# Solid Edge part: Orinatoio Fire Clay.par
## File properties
Title: Orinatoio
Author: DESYS
Template: iso part.par
Last saved by: s.pallini
Revision: 16
Application: Solid Edge
Tipo di contenuto documento: 0
Accuracy: 0,990
Document Number: 2014
Revision: 0
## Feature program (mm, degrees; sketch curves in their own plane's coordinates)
lofted protrusion "unnamed LoftedProtrusion 1"
sketch for "unnamed Protrusion 1" plane through (0, 0, 0) normal (0, -1, 0) x-axis (1, 0, 0)
  line (-19.3163, -75) -> (-440, -75)
  line (-440, -75) -> (-440, 75)
  line (-440, 75) -> (-19.3163, 75)
  line (-19.3163, 75) -> (-19.3163, -75)
  dimension (linear) = 440
extrude "unnamed Protrusion 1" add finite 155 along -normal
lofted cutout "unnamed LoftedCutout 1"
sketch for "ScavoEstrusione_1" plane through (43.6224, 155.3688, -0.1014) normal (0.615661, 0.788011, 0) x-axis (0, 0, -1)
  bspline degree 3 poles (0.466, 143.238) (-31.5699, 143.3592) (-62.3959, 125.2931) (-103.6679, 69.2618) (-114.958, 31.5333) (-115.2445, -44.1871) (-104.2401, -81.9998) (-63.3932, -138.3418) (-32.7047, -156.6406) (31.3671, -156.8829) (62.1931, -138.8169) (103.4651, -82.7856) (114.7552, -45.0571) (115.0417, 30.6633) (104.0373, 68.4761) (63.1903, 124.818) (32.5019, 143.1168) (0.466, 143.238) knots 0 0.125 0.25 0.375 0.5 0.625 0.75 0.875 1 multiplicities 4 2 2 2 2 2 2 2 4
extrude "ScavoEstrusione_1" cut finite 55 along -normal
fillet "Rotondo_2" radius 25
thinwall "Spessoramento_7"  Thickness = 10 mm
sketch for "unnamed Protrusion 2" plane through (-104.9962, 0, 0) normal (0, -1, 0) x-axis (0, 0, 1)
  line (-96.4961, -226.0512) -> (96.4961, -226.0512)
extrude "unnamed Protrusion 2" add through along -normal
fillet "Rotondo_3" radius 25
sketch for "Foro_1" plane through (-104.9962, 0, 0.101) normal (0, -1, 0) x-axis (0, 0, 1)
  hole centre (-0.101, -269.9962) bore radius 15
hole "Foro_1" diameter 30 finite  CounterBoreDepth = 12 mm
sketch for "ProtrusioneEstrusa_4" plane through (-104.9962, 50, 0.101) normal (0, -1, 0) x-axis (-1, 0, 0)
  circle centre (40.0038, 0.101) radius 22.5
extrude "ProtrusioneEstrusa_4" add finite 90 along -normal  Profile_Plane1_Distance = 50 mm
sketch for "Foro_2" plane through (-125, 50, 0) normal (0, -1, 0) x-axis (-1, 0, 0)
  hole centre (20, 0) bore radius 17.5
hole "Foro_2" diameter 35 finite
sketch for "unnamed Protrusion 3" #1 plane through (-104.9962, 0, 0.101) normal (0, -1, 0) x-axis (-1, 0, 0)
  line (302.5038, 65.101) -> (325.0038, 65.101)
  line (325.0038, 65.101) -> (325.0038, 42.601)
sketch for "unnamed Protrusion 3" #2 plane through (-104.9962, 0, 0.101) normal (0, -1, 0) x-axis (-1, 0, 0)
  line (325.0038, -64.899) -> (302.5038, -64.899)
  line (325.0038, -42.399) -> (325.0038, -64.899)
extrude "unnamed Protrusion 3" add through along -normal
sketch for "Foro_3" plane through (-104.9962, 0, 0.101) normal (0, -1, 0) x-axis (-1, 0, 0)
  hole centre (320.0038, 60.101) bore radius 5
hole "Foro_3" diameter 10 finite
sketch for "unnamed Hole 1" plane through (-104.9962, 0, 0.101) normal (0, -1, 0) x-axis (-1, 0, 0)
  hole centre (320.0038, -59.899) bore radius 5
hole "unnamed Hole 1" finite
pattern "unnamed Pattern 1" of "Foro_3", "unnamed Hole 1"
fillet "Rotondo_6" radius 10
fillet "Rotondo_7" radius 10
fillet "Rotondo_8" radius 3
fillet "Rotondo_9" radius 10
fillet "Rotondo_10" radius 5
fillet "Rotondo_11" radius 10
sketch for "unnamed Protrusion 4" plane through (-132.686, 140, 0.1259) normal (0, 1, 0) x-axis (-1, 0, 0)
  line (-2.473, 16.8328) -> (-2.473, 9.2334)
  line (-2.473, -9.4852) -> (-2.473, -17.0846)
extrude "unnamed Protrusion 4" add to key point along +normal
fillet "Rotondo_12" radius 5
fillet "Rotondo_13" radius 3
fillet "Rotondo_14" radius 3
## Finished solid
Body 1: solid body, 89 faces, 181 edges, 94 vertices.
  Faces by surface: plane 26, blend 24, cylinder 24, torus 7, offset 3, sphere 2, spline 2, swept 1
  Edges by curve: intersection 71, circle 60, line 48, ellipse 1, spline 1
Bounding box of the edges (mm; curved faces can reach further): 693.085 x 301.754 x 298.185, from (-440, 0, -149.094) to (253.0847, 301.754, 149.0913).
Cylindrical faces by radius (mm): R3 x6, R5 x2, R10 x8, R15 x1, R17.5 x2, R22.5 x3, R25 x2
Toroidal faces (ring radius, tube radius in mm): R7 r3 x2, R19.5 r3 x3, R32.5 r10 x2
Spherical faces by radius (mm): R10 x2
Planar faces by outward normal: +x 3, +y 2, +z 2, -x 3, -y 8, -z 2, oblique 6
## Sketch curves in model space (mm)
ellipse centre (48.9509, 151.2057, 0) radii 130.0009, 95.0007
ellipse centre (111.5009, 178.4774, 0) radii 162.5007, 110.0005
ellipse centre (101.6508, 186.1732, 0) radii 200, 150
line (210, 0, 0) -> (259.2529, 63.0409, 0)
ellipse centre (0, 0, 0) radii 210, 132.5
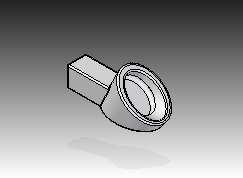
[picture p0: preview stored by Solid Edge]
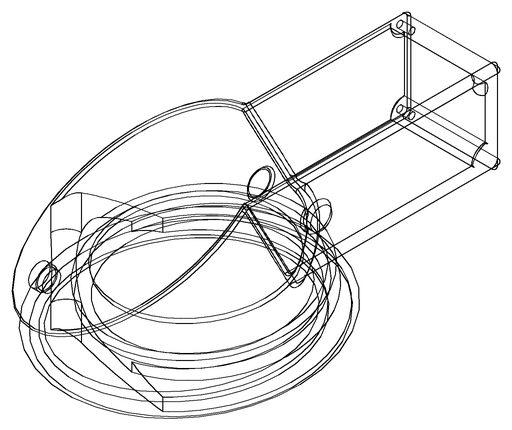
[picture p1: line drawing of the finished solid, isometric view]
